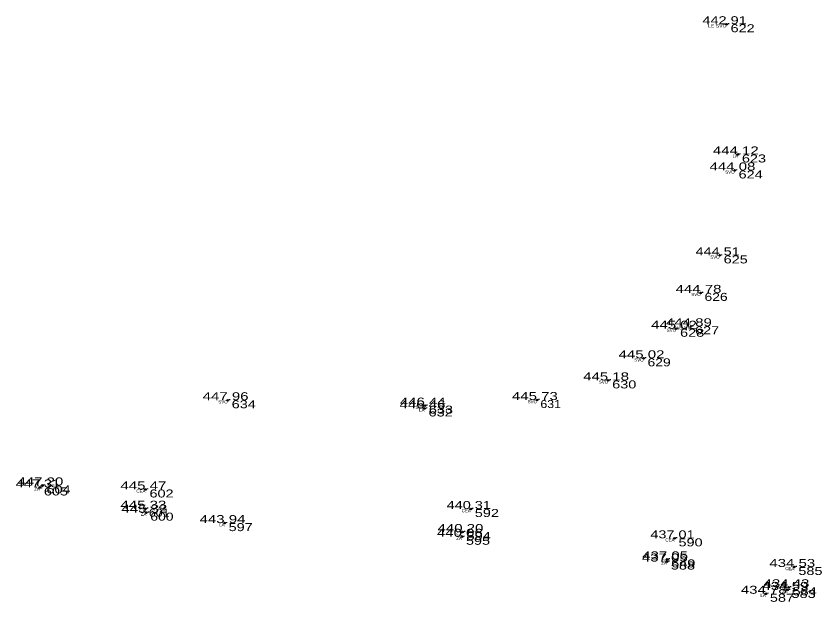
# Model space of a CAD drawing. Extents: x -639373 to -639056, y -1138651 to -1138359.
# Drawn here: x -639373.3 to -639297.8, y -1138578.8 to -1138523.9 of the extents above; entities that cross this region are included whole.
import ezdxf
from ezdxf.enums import TextEntityAlignment as Align

# ---------------------------------------------------------------- set-up
doc = ezdxf.new("R2010")
doc.units = 0
doc.header["$LTSCALE"] = 0.3
doc.header["$PDMODE"] = 32
doc.header["$PDSIZE"] = 0.15
for name, color, linetype in [('11', 7, 'Continuous'), ('12', 7, 'Continuous'), ('13', 7, 'Continuous'), ('57', 7, 'Continuous')]:
    doc.layers.add(name, color=color, linetype=linetype)

msp = doc.modelspace()

# ---------------------------------------------------------------- linework, layer by layer
at = {"layer": '11'}
for p in [(-639306.73, -1138524.65), (-639305.67, -1138536.85), (-639305.98, -1138538.35), (-639307.38, -1138546.31), (-639309.16, -1138549.82), (-639311.46, -1138553.18), (-639310.06, -1138552.95), (-639314.5, -1138555.95), (-639317.82, -1138558.02), (-639353.46, -1138559.88), (-639324.49, -1138559.86), (-639335.02, -1138560.65), (-639334.99, -1138560.38), (-639370.81, -1138567.86), (-639371.05, -1138568.05), (-639361.16, -1138568.24), (-639361.16, -1138570.04), (-639330.69, -1138570.07), (-639361.07, -1138570.41), (-639353.75, -1138571.39), (-639331.46, -1138572.23), (-639331.52, -1138572.67), (-639311.61, -1138572.82), (-639312.32, -1138574.99), (-639312.29, -1138574.79), (-639300.38, -1138575.5), (-639301.02, -1138577.65), (-639300.92, -1138577.4), (-639303.05, -1138578.01)]:
    msp.add_point(p, dxfattribs=at)

# ---------------------------------------------------------------- texts
at = {"layer": '12'}
for s, width, p in [('442.91 ', 1.35, (-639306.729, -1138524.65)), ('444.12 ', 1.4, (-639305.67, -1138536.85)), ('444.08 ', 1.4, (-639305.98, -1138538.35)), ('444.51 ', 1.35, (-639307.379, -1138546.31)), ('444.78 ', 1.4, (-639309.16, -1138549.82)), ('445.02 ', 1.4, (-639311.46, -1138553.18)), ('444.89 ', 1.4, (-639310.06, -1138552.95)), ('445.02 ', 1.4, (-639314.5, -1138555.95)), ('445.18 ', 1.4, (-639317.82, -1138558.02)), ('447.96 ', 1.4, (-639353.459, -1138559.88)), ('445.73 ', 1.4, (-639324.49, -1138559.86)), ('446.46 ', 1.4, (-639335.019, -1138560.65)), ('446.44 ', 1.4, (-639334.99, -1138560.38)), ('447.31 ', 1.35, (-639371.049, -1138568.05)), ('447.20 ', 1.4, (-639370.81, -1138567.86)), ('445.47 ', 1.4, (-639361.16, -1138568.24)), ('445.33 ', 1.4, (-639361.16, -1138570.04)), ('440.31 ', 1.35, (-639330.689, -1138570.07)), ('445.32 ', 1.4, (-639361.07, -1138570.41)), ('443.94 ', 1.4, (-639353.75, -1138571.39)), ('440.20 ', 1.4, (-639331.46, -1138572.23)), ('440.06 ', 1.4, (-639331.519, -1138572.67)), ('437.01 ', 1.35, (-639311.609, -1138572.82)), ('437.05 ', 1.4, (-639312.32, -1138574.99)), ('437.05 ', 1.4, (-639312.29, -1138574.79)), ('434.53 ', 1.4, (-639300.38, -1138575.5)), ('434.43 ', 1.4, (-639300.92, -1138577.4)), ('434.78 ', 1.4, (-639303.05, -1138578.01)), ('434.59 ', 1.4, (-639301.02, -1138577.65))]:
    msp.add_text(s, height=0.75, dxfattribs=dict(at, width=width)).set_placement(p, align=Align.CENTER)
at = {"layer": '13'}
for s, width, p in [(' 622', 1.35, (-639306.73, -1138525.4)), (' 623', 1.35, (-639305.67, -1138537.6)), (' 624', 1.35, (-639305.98, -1138539.1)), (' 625', 1.35, (-639307.38, -1138547.06)), (' 626', 1.3, (-639309.16, -1138550.57)), (' 628', 1.35, (-639311.46, -1138553.93)), (' 627', 1.35, (-639310.06, -1138553.7)), (' 629', 1.3, (-639314.5, -1138556.7)), (' 630', 1.35, (-639317.82, -1138558.77)), (' 634', 1.35, (-639353.46, -1138560.63)), (' 631', 1.15, (-639324.49, -1138560.61)), (' 632', 1.35, (-639335.02, -1138561.4)), (' 633', 1.35, (-639334.99, -1138561.13)), (' 605', 1.35, (-639371.05, -1138568.8)), (' 604', 1.35, (-639370.81, -1138568.61)), (' 602', 1.35, (-639361.16, -1138568.99)), (' 601', 1.15, (-639361.16, -1138570.79)), (' 592', 1.35, (-639330.69, -1138570.82)), (' 600', 1.3, (-639361.07, -1138571.16)), (' 597', 1.35, (-639353.75, -1138572.14)), (' 594', 1.35, (-639331.46, -1138572.98)), (' 595', 1.35, (-639331.52, -1138573.42)), (' 590', 1.35, (-639311.61, -1138573.57)), (' 588', 1.35, (-639312.32, -1138575.74)), (' 649', 1.35, (-639312.29, -1138575.54)), (' 585', 1.35, (-639300.38, -1138576.25)), (' 584', 1.35, (-639300.92, -1138578.15)), (' 587', 1.35, (-639303.05, -1138578.76)), (' 583', 1.35, (-639301.02, -1138578.4))]:
    msp.add_text(s, height=0.75, dxfattribs=dict(at, width=width)).set_placement(p)
at = {"layer": '57'}
for s, width, p in [('LE SVO', 1.2, (-639306.729, -1138524.95)), ('SVO', 0.95, (-639305.979, -1138538.65)), ('SVO', 0.95, (-639307.379, -1138546.61)), ('SVO', 0.95, (-639309.159, -1138550.12)), ('SVO', 0.95, (-639311.459, -1138553.48)), ('SLB NN', 1.15, (-639310.059, -1138553.25)), ('SVO', 0.95, (-639314.499, -1138556.25)), ('SVO', 0.95, (-639317.819, -1138558.32)), ('SVO', 0.95, (-639353.459, -1138560.18)), ('SVO', 0.95, (-639324.489, -1138560.16)), ('SVO', 0.95, (-639334.989, -1138560.68)), ('CE', 0.9, (-639370.81, -1138568.16)), ('CE', 0.9, (-639361.16, -1138570.34)), ('CE', 0.9, (-639331.46, -1138572.53)), ('CE', 0.9, (-639312.29, -1138575.09)), ('CE', 0.9, (-639300.92, -1138577.7))]:
    msp.add_text(s, height=0.3, dxfattribs=dict(at, width=width)).set_placement(p, align=Align.RIGHT)
for s, p in [('LA', (-639305.67, -1138537.15)), ('LA', (-639335.02, -1138560.95)), ('ZA', (-639371.05, -1138568.35)), ('CEA', (-639361.16, -1138568.54)), ('CEA', (-639330.69, -1138570.37)), ('ZA', (-639361.07, -1138570.71)), ('LA', (-639353.75, -1138571.69)), ('ZA', (-639331.52, -1138572.97)), ('CEA', (-639311.61, -1138573.12)), ('ZA', (-639312.32, -1138575.29)), ('CEA', (-639300.38, -1138575.8)), ('LA', (-639303.05, -1138578.31)), ('ZA', (-639301.02, -1138577.95))]:
    msp.add_text(s, height=0.3, dxfattribs=at).set_placement(p, align=Align.RIGHT)

doc.saveas('drawing.dxf')
